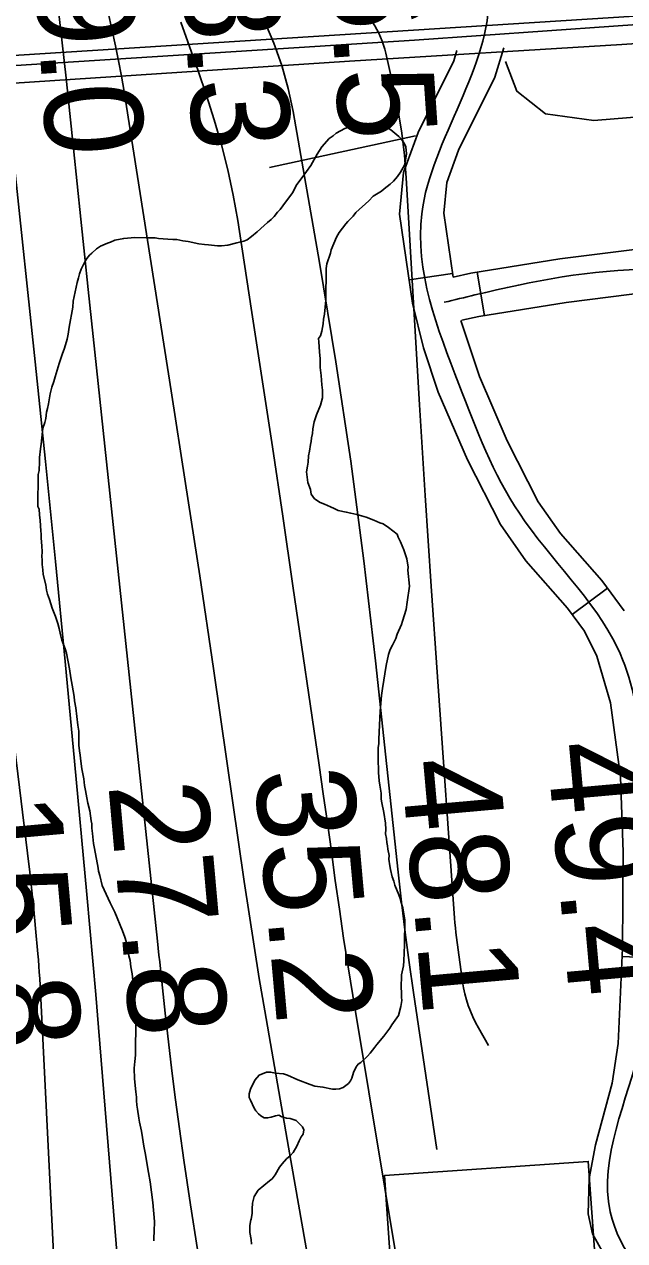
# Model space of a CAD drawing. Extents: x 3313442 to 3351311, y 721974 to 747360.
# Drawn here: x 3324727 to 3325136, y 729113 to 729942 of the extents above; entities that cross this region are included whole.
import ezdxf

# ---------------------------------------------------------------- set-up
doc = ezdxf.new("R2010")
doc.units = 0
for name, color, linetype in [('V-BLDG-OTLN', 7, 'Continuous'), ('V-BRDG-OTLN', 7, 'Continuous'), ('V-RIVR-RANG', 7, 'Continuous'), ('V-ROAD-CNTR', 7, 'Continuous'), ('V-SITE-VEGE', 7, 'Continuous'), ('V-TOPO-MAJR', 7, 'Continuous'), ('V-TOPO-MINR', 7, 'Continuous'), ('V-TOPO-SHOR', 7, 'Continuous')]:
    doc.layers.add(name, color=color, linetype=linetype)

msp = doc.modelspace()

# ---------------------------------------------------------------- linework, layer by layer
at = {"layer": 'V-BLDG-OTLN'}
msp.add_lwpolyline([(3324979.84, 729052.72), (3324972.54, 729157.11), (3325111.5, 729166.83), (3325118.81, 729062.45)], close=True, dxfattribs=at)
at = {"layer": 'V-BRDG-OTLN'}
for points in [[(3325676.61, 729961.93), (3325403.23, 729945.42), (3325134.28, 729927.72), (3324948.68, 729916.36), (3324716.77, 729901.2), (3324586.68, 729892.87), (3324582.42, 729979.53), (3324713.54, 729987.61), (3324937.54, 730002.27), (3325170.02, 730017.23), (3325371.06, 730029.8), (3325611.64, 730045.26), (3325891.58, 730062.67)], [(3320029.11, 729613.8), (3320339.22, 729634.27), (3320661.41, 729653.97), (3320967.6, 729674.61), (3321254.1, 729691.76), (3321493.35, 729708.2), (3321721.78, 729722.63), (3322170.54, 729751.36), (3322654.03, 729782.08), (3323222.6, 729817.79), (3323823.97, 729856.26), (3324302.83, 729887.22), (3324624.44, 729907.32), (3324993.14, 729930.83), (3325309.56, 729952.91), (3325623.66, 729972.5), (3325900.26, 729988.64)]]:
    msp.add_lwpolyline(points, dxfattribs=at)
at = {"layer": 'V-ROAD-CNTR'}
for p, q in [((3325040.64, 729743), (3325035.83, 729772.61)), ((3325019.02, 729771.78), (3324989.33, 729767.5)), ((3325124.51, 729557.34), (3325100.39, 729539.5)), ((3325164.42, 729305.07), (3325134.44, 729306.35))]:
    msp.add_line(p, q, dxfattribs=at)
for points in [[(3327244.32, 730080.97), (3325899.84, 729995.27), (3321914.87, 729742.58)], [(3325021.99, 729923.68), (3325019.83, 729916.59), (3324995.54, 729867.78), (3324985.54, 729840.53), (3324982.88, 729812.14), (3324991.63, 729751.57), (3324999.16, 729721.02), (3325009.26, 729690.9), (3325029.05, 729644.89), (3325051.62, 729600.66), (3325068.84, 729575.95), (3325097.3, 729543.68), (3325108.85, 729528.06), (3325117.35, 729511.11), (3325126.64, 729479.13), (3325133.54, 729428.9), (3325135.35, 729377.58), (3325134.69, 729312.1), (3325131.91, 729247.11), (3325127.73, 729220.19), (3325116.42, 729178.06), (3325112.07, 729155.23), (3325111.41, 729131.17), (3325114.31, 729117.4), (3325124.93, 729098.43)], [(3325053.92, 729925.55), (3325047.81, 729905.47), (3325023.14, 729855.89), (3325015.05, 729833.85), (3325013.08, 729812.89), (3325019.38, 729769.25)], [(3325658.28, 729822.55), (3325559.88, 729844.76), (3325493.97, 729854.26), (3325460.14, 729856.59), (3325426, 729855.59), (3325401.37, 729851.19), (3325367.02, 729839.46), (3325333.75, 729825.55), (3325315.67, 729816.24), (3325291.28, 729801.02), (3325280.26, 729795.35), (3325269.37, 729791.76), (3325242.55, 729788.69), (3325153.82, 729789.47), (3325092.19, 729781.78), (3325031.34, 729771.88), (3325019.38, 729769.25)], [(3325329.81, 729789.7), (3325306.1, 729774.9), (3325291.88, 729767.6), (3325275.85, 729762.3), (3325244.13, 729758.67), (3325155.55, 729759.45), (3325096.46, 729752.08), (3325036.98, 729742.4), (3325025.41, 729739.86)], [(3325024.54, 729739.67), (3325037.31, 729701.61), (3325056.22, 729657.65), (3325077.41, 729616.13), (3325092.48, 729594.51), (3325120.66, 729562.55), (3325135.88, 729541.97)]]:
    msp.add_lwpolyline(points, dxfattribs=at)
for points in [[(3326478.04, 730210.35), (3326482.35, 730403.29), (3326476.58, 730549.39), (3326473.61, 730637.71), (3326464.08, 730712.16), (3326370.96, 730713.71), (3326297.71, 730698.23), (3326169.71, 730725.9), (3326116.45, 730727.88), (3325982.64, 730689.67), (3325835.77, 730656.61), (3325666.24, 730661.4), (3325490.23, 730637.83), (3325403.5, 730634.84), (3325340.74, 730586.21), (3325201.43, 730523.99), (3325133.39, 730524.77), (3325012.9, 730513.46), (3324963.14, 730471.34), (3324981.93, 730365.88), (3324989.76, 730188.11), (3325009.72, 730055.84), (3325043.42, 729962.4), (3324997.98, 729812.51), (3325023.28, 729696.25), (3325064.51, 729608.4), (3325131.37, 729516.61), (3325150.36, 729377.77), (3325146.87, 729245.63), (3325126.45, 729132.53), (3325181.34, 729069.88), (3325338.87, 729062.31), (3325343.56, 728961.08), (3325372.85, 728878.06), (3325434.63, 728797.89), (3325537.34, 728748.77), (3325622.45, 728705.03), (3325714.6, 728675.45), (3325802.67, 728663.42), (3325976.26, 728695.07), (3326194.29, 728726.31), (3326466.63, 728765.32), (3326625.11, 728781.99), (3326781.78, 728849.74), (3326900.23, 728862.4), (3326981.75, 728872.83), (3327122.94, 728906.43), (3327349.99, 728934.63), (3327499.05, 728974.33), (3327515.65, 728986.69), (3327498, 729057.12), (3327490.77, 729119.3), (3327510.96, 729180.47), (3327588.76, 729283.84), (3327686.92, 729357.21), (3327753.03, 729377.43), (3327803.43, 729380.44), (3327847.87, 729388.87), (3327934.83, 729389.79), (3328039.14, 729390.23), (3328120.59, 729395.25), (3328249.21, 729403.96), (3328319.73, 729407.13), (3328384.24, 729401.49), (3328424.57, 729387.35), (3328470.08, 729368.59), (3328549.26, 729327.46), (3328661.09, 729275.68), (3328877.57, 729175.26), (3328980.19, 729125.77), (3329049.22, 729101.24), (3329067.8, 729104.63), (3329088.99, 729118.36), (3329113.61, 729147.02), (3329153.45, 729227.36), (3329182.49, 729301.19), (3329201.64, 729378.5), (3329199.66, 729471.18), (3329192.73, 729551.54), (3329166.92, 729646.66), (3329121.79, 729727.55), (3329091.49, 729778.71), (3329016.19, 729835.66), (3328941.73, 729880.13), (3328875.38, 729924.2), (3328789.67, 729967.9), (3328700.81, 730000.01), (3328643.56, 730009.51), (3328577.01, 730014.29), (3328435.19, 729993.91), (3328288.99, 729968.49), (3328169.46, 729944.48), (3328087.81, 729917.23), (3328042.9, 729880.41), (3327999.54, 729814.48), (3327967.22, 729727.08), (3328009.37, 729621.12)], [(3327455.61, 729777.77), (3327299.2, 729747.93), (3327231.33, 729750.07), (3327172.26, 729812.85), (3327115.65, 729890.62), (3326929.18, 729884.74), (3326778.26, 729875.26), (3326677.82, 729882.4), (3326518.7, 729881.16), (3326341.77, 729822.32), (3326240.47, 729767.06), (3326176.75, 729745.99), (3326056.79, 729783.32), (3325905.3, 729813.94), (3325785.04, 729804.98), (3325688.89, 729803.53), (3325557.16, 729830), (3325427.55, 729840.63), (3325340.08, 729811.94), (3325272.61, 729777.03), (3325154.68, 729774.46), (3325034.16, 729757.14), (3325013.34, 729752.14)], [(3325351.41, 729592.27), (3325302.24, 729587.13), (3325244.43, 729589.35), (3325190.04, 729576.79), (3325151.9, 729539.75), (3325158.25, 729396.51), (3325150.36, 729377.77)]]:
    msp.add_spline(points, degree=3, dxfattribs=at)
at = {"layer": 'V-SITE-VEGE'}
for points in [[(3324895.29, 729808.5), (3324897.42, 729810.59), (3324899.56, 729813.47), (3324901.43, 729815.3), (3324903.3, 729817.93), (3324909.98, 729826.84), (3324912.94, 729832.35), (3324916.42, 729837.07), (3324922.3, 729845.46), (3324926.6, 729853.08), (3324929.81, 729858.06), (3324934.88, 729863.82), (3324937.54, 729865.64), (3324939.67, 729867.47), (3324945.5, 729870.58), (3324952.92, 729872.89), (3324955.03, 729873.13), (3324963.75, 729873.84), (3324968.49, 729873.53), (3324972.71, 729872.17), (3324976.9, 729869.76), (3324982.4, 729865.22), (3324983.98, 729863.62), (3324986.32, 729860.17), (3324987.09, 729858.05), (3324987.57, 729853.29), (3324987, 729849.07), (3324986.18, 729845.65), (3324983.49, 729840.92), (3324981.35, 729837.78), (3324978.69, 729834.63)], [(3324978.69, 729834.63), (3324976.55, 729832.54), (3324972.3, 729829.41), (3324970.44, 729827.85), (3324964.86, 729824.47), (3324961.93, 729821.33), (3324953.14, 729813.23), (3324951.27, 729810.88), (3324947.54, 729807.21), (3324946.21, 729805.64), (3324941.67, 729799.61), (3324939.79, 729796.46), (3324936.27, 729787.79), (3324935.73, 729785.68), (3324933.28, 729778.31), (3324932.72, 729775.15), (3324932.52, 729753.51), (3324931.64, 729744.01), (3324931.08, 729740.59), (3324930.78, 729737.42), (3324929.95, 729732.42), (3324928.86, 729729.26), (3324927.52, 729727.43), (3324927.77, 729725.31), (3324928.23, 729718.44), (3324928.71, 729713.69), (3324928.65, 729707.62), (3324929.4, 729702.33), (3324929.87, 729695.99), (3324930.35, 729692.29), (3324930.31, 729687.02), (3324928.94, 729682.01), (3324926.24, 729675.44), (3324924.61, 729670.7), (3324923.77, 729665.96), (3324923.48, 729662.8), (3324922.92, 729659.9), (3324922.64, 729657.26), (3324922.09, 729655.15), (3324921.52, 729650.67), (3324920.7, 729647.51), (3324920.66, 729643.29), (3324920.1, 729640.39), (3324919.54, 729636.7), (3324920.26, 729629.3), (3324922.06, 729624.53), (3324922.56, 729621.37), (3324924.91, 729618.18), (3324928.84, 729615.76), (3324931.74, 729614.68), (3324935.68, 729612.79), (3324938.31, 729611.71), (3324940.93, 729610.37), (3324946.47, 729609.26), (3324949.63, 729608.44), (3324953.84, 729607.6), (3324960.16, 729605.7), (3324965.42, 729603.8), (3324969.36, 729601.92), (3324971.73, 729601.1), (3324975.4, 729598.69), (3324981.17, 729594.15), (3324981.94, 729592.03), (3324983.49, 729588.85), (3324985.82, 729583.55), (3324987.1, 729579.31), (3324987.87, 729577.46), (3324988.61, 729571.65), (3324988.59, 729569.53), (3324989.54, 729558.7), (3324988.12, 729547.89), (3324987.28, 729542.89), (3324984.83, 729534.99), (3324984.28, 729532.62), (3324981.31, 729526.05), (3324980.23, 729523.16), (3324978.08, 729518.43), (3324976.46, 729515.54), (3324975.38, 729512.11), (3324973.72, 729504.74), (3324971.2, 729488.93), (3324970.62, 729484.18), (3324969.73, 729473.63), (3324968.76, 729454.37), (3324968.73, 729451.47), (3324968.18, 729448.57), (3324968.34, 729438.01), (3324968.58, 729435.64), (3324968.54, 729431.67), (3324969.02, 729426.13), (3324969.52, 729423.22), (3324970.26, 729417.67), (3324970.22, 729413.71), (3324970.73, 729411.07), (3324972.25, 729404.45), (3324973.23, 729397.32), (3324973.46, 729392.83), (3324973.17, 729389.93), (3324973.93, 729386.75), (3324974.17, 729384.11), (3324974.67, 729381.73)], [(3324766.38, 729434.38), (3324765.64, 729439.4), (3324765.15, 729443.63), (3324764.65, 729446.53), (3324764.16, 729450.5), (3324764.25, 729460), (3324763.5, 729463.97), (3324762.29, 729475.86), (3324761.28, 729480.61), (3324761.04, 729483.52), (3324759.79, 729491.19), (3324758.79, 729496.21), (3324757.79, 729502.29), (3324755.78, 729513.13), (3324755.01, 729516.05), (3324752.69, 729521.87), (3324751.67, 729525.58), (3324750.92, 729529.81), (3324749.9, 729533.25), (3324748.36, 729538.01), (3324746.04, 729543.84), (3324744.25, 729549.67), (3324742.96, 729553.38), (3324742.19, 729556.02), (3324741.7, 729559.72), (3324739.92, 729566.6), (3324739.68, 729569.77), (3324739.19, 729573.47), (3324739.22, 729576.64), (3324738.98, 729579.02), (3324739.27, 729582.18), (3324739.05, 729586.14), (3324738.57, 729591.43), (3324738.59, 729594.06), (3324738.35, 729596.44), (3324737.89, 729603.58), (3324737.4, 729607.27), (3324737.17, 729611.24), (3324736.4, 729613.09), (3324736.6, 729634.73), (3324737.16, 729637.63), (3324737.48, 729643.44), (3324737.5, 729646.34), (3324738.09, 729652.4), (3324738.65, 729655.57), (3324739.8, 729666.38), (3324741.16, 729670.32), (3324741.71, 729672.96), (3324742.28, 729677.18), (3324742.83, 729679.81), (3324743.65, 729682.97), (3324744.78, 729689.82), (3324745.88, 729694.3), (3324747.23, 729698.25), (3324748.05, 729701.41), (3324750.78, 729710.35), (3324752.95, 729716.67), (3324754.57, 729720.87), (3324756.21, 729726.93), (3324757.04, 729730.35), (3324757.61, 729735.1), (3324760.11, 729748.8), (3324760.42, 729753.02), (3324763.18, 729765.67), (3324764, 729768.83), (3324764.81, 729771.46), (3324765.9, 729774.62), (3324766.71, 729776.45), (3324768.32, 729779.61), (3324769.67, 729781.97), (3324771.54, 729784.33), (3324773.13, 729785.63), (3324776.33, 729788.51), (3324778.98, 729790.33), (3324783.75, 729792.39), (3324785.87, 729793.17), (3324788.79, 729794.46), (3324794.87, 729795.72), (3324802.53, 729796.18), (3324810.45, 729796.1), (3324816.25, 729796.05), (3324818.62, 729795.5), (3324824.96, 729795.17), (3324828.38, 729794.88), (3324831.02, 729794.85), (3324835.24, 729794.02), (3324838.67, 729793.46), (3324846.04, 729792.07), (3324850, 729791.51), (3324852.64, 729791.22), (3324858.7, 729790.63), (3324861.6, 729790.6), (3324865.83, 729791.09), (3324871.92, 729792.62), (3324876.68, 729793.89), (3324879.06, 729794.66), (3324881.98, 729797.01), (3324885.71, 729800.14), (3324890.5, 729804.58), (3324892.9, 729806.41), (3324895.29, 729808.5)], [(3324815.35, 729112.68), (3324815.36, 729114.8), (3324815.67, 729119.02), (3324815.73, 729125.88), (3324814.8, 729138.82), (3324812.82, 729152.83), (3324811.82, 729159.17), (3324809.58, 729172.65), (3324808.56, 729177.15), (3324807.56, 729182.97), (3324807.08, 729187.46), (3324805.55, 729193.55), (3324805.04, 729196.19), (3324804.31, 729202.27), (3324803.81, 729205.18), (3324803.58, 729208.35), (3324803.6, 729210.46), (3324803.1, 729214.16), (3324802.13, 729223.14), (3324801.94, 729230.27), (3324802.51, 729234.75), (3324802.81, 729239.24), (3324803.04, 729263.52), (3324802.84, 729270.38), (3324802.14, 729279.36), (3324800.7, 729294.69), (3324799.69, 729299.45), (3324799.2, 729303.67), (3324798.44, 729306.85), (3324796.42, 729316.63), (3324795.65, 729319.55), (3324794.11, 729323.78), (3324788.69, 729336.5), (3324785.58, 729342.87), (3324780.15, 729354.8), (3324778.63, 729361.67), (3324777.6, 729364.59), (3324777.36, 729366.7), (3324774.84, 729379.92), (3324774.35, 729383.36), (3324773.62, 729390.23), (3324773.13, 729393.93), (3324773.16, 729396.83), (3324772.65, 729398.95), (3324771.66, 729405.56), (3324770.39, 729410.85), (3324769.63, 729414.55), (3324768.88, 729419.57), (3324768.12, 729423.01), (3324767.64, 729427.5), (3324766.38, 729434.38)], [(3324974.67, 729381.73), (3324974.92, 729379.62), (3324975.66, 729375.12), (3324975.64, 729372.75), (3324976.13, 729368.26), (3324976.63, 729365.61), (3324977.91, 729360.58), (3324978.94, 729357.67), (3324979.7, 729355.02), (3324982.27, 729348.4), (3324983.31, 729346.01), (3324983.82, 729343.9), (3324985.1, 729339.66), (3324986.34, 729331.2), (3324986.18, 729314.31), (3324985.81, 729303.5), (3324985.52, 729300.07), (3324984.14, 729294.01), (3324984.05, 729284.77), (3324984.29, 729282.4), (3324984.26, 729278.7), (3324984.5, 729276.32), (3324983.67, 729272.37), (3324982.03, 729266.31), (3324977.48, 729259.76), (3324976.14, 729257.66), (3324972.13, 729252.16), (3324967.32, 729246.39), (3324965.98, 729244.56), (3324962.78, 729240.63), (3324960.92, 729238.53), (3324956.38, 729234.09), (3324954.53, 729233.05), (3324953.19, 729231.22), (3324951.57, 729227.27), (3324950.22, 729223.59), (3324949.41, 729221.75), (3324948.07, 729219.92), (3324946.21, 729218.61), (3324944.35, 729217.05), (3324941.96, 729216.28), (3324939.32, 729216.04), (3324937.21, 729216.06), (3324930.62, 729217.44), (3324925.09, 729218.02), (3324921.93, 729219.11), (3324913.51, 729222.35), (3324906.42, 729225.59), (3324903.78, 729226.4), (3324897.98, 729226.99), (3324895.09, 729227.54), (3324892.18, 729227.57), (3324887.15, 729225.51), (3324884.21, 729222.1), (3324881.25, 729216.06), (3324880.43, 729212.9), (3324880.41, 729210.26), (3324881.18, 729208.41), (3324883.77, 729203.1), (3324884.81, 729201.24), (3324886.64, 729199.11), (3324888.21, 729197.78), (3324890.57, 729196.44), (3324892.95, 729196.42), (3324895.33, 729196.92), (3324898.24, 729197.95), (3324900.62, 729198.19), (3324902.72, 729197.12), (3324905.88, 729196.29), (3324908.25, 729196.01), (3324912.46, 729194.65), (3324916.64, 729190.39), (3324917.68, 729188.26), (3324917.12, 729185.36), (3324915.79, 729183.53), (3324914.44, 729180.91), (3324912.82, 729177.22), (3324910.41, 729172.76), (3324908.27, 729170.67), (3324905.88, 729168.58), (3324902.94, 729165.18), (3324901.07, 729162.82), (3324898.12, 729157.56), (3324895.98, 729154.95), (3324894.12, 729153.65), (3324886.41, 729147.12), (3324883.73, 729142.92), (3324882.63, 729138.44), (3324882.33, 729134.49), (3324882.3, 729131.58), (3324881.73, 729127.1), (3324881.47, 729127.11), (3324880.9, 729122.89), (3324880.86, 729118.4), (3324881.61, 729113.64), (3324881.84, 729110.47)]]:
    msp.add_lwpolyline(points, dxfattribs=at)
at = {"layer": 'V-TOPO-MAJR'}
msp.add_lwpolyline([(3324845.03, 729106.86), (3324840.34, 729137.21), (3324835.88, 729167.59), (3324832.86, 729189.07), (3324830.19, 729208.75), (3324827.65, 729228.45), (3324825.31, 729248.17), (3324823.1, 729267.9), (3324819.89, 729298.01), (3324819.39, 729302.7), (3324818.89, 729307.4), (3324818.39, 729312.09), (3324817.89, 729316.78), (3324770.66, 729760.84), (3324768.13, 729784.84), (3324765.62, 729808.84), (3324763.15, 729832.84), (3324760.7, 729856.85), (3324758.21, 729880.86), (3324755.63, 729904.85), (3324752.91, 729928.83), (3324750.11, 729952.8)], dxfattribs=at)
at = {"layer": 'V-TOPO-MINR'}
for points in [[(3324800.84, 728974.44), (3324777.7, 729257.93), (3324775.81, 729280.6), (3324773.87, 729303.26), (3324771.85, 729325.91), (3324769.79, 729348.56), (3324761.34, 729439.43), (3324754.9, 729507.5), (3324748.3, 729575.55), (3324741.46, 729643.58), (3324734.46, 729711.6), (3324720.29, 729847.02), (3324717.39, 729876.02), (3324714.69, 729905.03), (3324712.26, 729934.06), (3324710.02, 729963.11), (3324687.63, 730272.74), (3324687.41, 730275.62), (3324687.19, 730278.51), (3324686.96, 730281.39), (3324686.73, 730284.27), (3324686.38, 730288.4), (3324686.11, 730291.65), (3324658.43, 730619.77)], [(3324925.38, 729072.99), (3324916.14, 729124.68), (3324907.07, 729176.4), (3324890.99, 729269.3), (3324887.27, 729291.33), (3324883.68, 729313.38), (3324880.28, 729335.46), (3324877, 729357.56), (3324865.2, 729439.54), (3324856, 729502.63), (3324846.63, 729565.69), (3324837.02, 729628.72), (3324827.25, 729691.73), (3324796.83, 729885.47), (3324795.1, 729895.88), (3324793.27, 729906.26), (3324791.26, 729916.62), (3324789.15, 729926.96), (3324784.32, 729949.57)], [(3325005.6, 728951.7), (3324950.92, 729279.81), (3324947.75, 729299.39), (3324944.7, 729318.99), (3324941.82, 729338.61), (3324939.07, 729358.25), (3324936.38, 729377.9), (3324933.64, 729397.55), (3324930.85, 729417.19), (3324928.02, 729436.82), (3324910.2, 729559.05), (3324903.24, 729606.36), (3324896.2, 729653.66), (3324889.05, 729700.94), (3324881.81, 729748.21), (3324872.6, 729807.87), (3324869.51, 729825.21), (3324865.91, 729842.43), (3324861.52, 729859.46), (3324856.61, 729876.38), (3324851.18, 729893.15), (3324845.58, 729909.87), (3324839.72, 729926.5), (3324833.69, 729943.07)], [(3325008.32, 729175.01), (3324992.35, 729281.86), (3324989.42, 729302.34), (3324986.66, 729322.84), (3324984.16, 729343.38), (3324981.83, 729363.94), (3324966.42, 729507.91), (3324958.46, 729575.94), (3324949.59, 729643.85), (3324939.39, 729711.57), (3324928.29, 729779.16), (3324910.33, 729882.08), (3324906.9, 729897.92), (3324902.64, 729913.5), (3324897.13, 729928.68), (3324890.8, 729943.6)], [(3325043.49, 729245.81), (3325036.55, 729257.85), (3325034.57, 729261.51), (3325032.73, 729265.24), (3325031.12, 729269.07), (3325029.64, 729272.97), (3325028.4, 729276.94), (3325027.32, 729280.95), (3325026.48, 729285.02), (3325025.8, 729289.13), (3325021.72, 729319.4), (3325021.31, 729322.69), (3325020.94, 729325.98), (3325020.63, 729329.28), (3325020.37, 729332.59), (3325008.7, 729496.96), (3325004.44, 729558.71), (3325000.34, 729620.48), (3324996.48, 729682.27), (3324992.78, 729744.06), (3324987.39, 729837.06), (3324986.14, 729852.31), (3324984.39, 729867.49), (3324981.91, 729882.57), (3324978.93, 729897.58), (3324973.51, 729921.8), (3324972.8, 729924.63), (3324971.98, 729927.42), (3324971.01, 729930.16), (3324969.94, 729932.86), (3324968.71, 729935.5), (3324967.38, 729938.09), (3324965.9, 729940.58), (3324964.31, 729943.03)], [(3324748.24, 729081.6), (3324744.56, 729154.36), (3324737.57, 729291.41), (3324737.33, 729295.64), (3324737.06, 729299.87), (3324736.73, 729304.1), (3324736.37, 729308.32), (3324734.8, 729325.53), (3324733.57, 729338.35), (3324732.27, 729351.16), (3324730.84, 729363.95), (3324729.33, 729376.74), (3324712.63, 729512.75)]]:
    msp.add_lwpolyline(points, dxfattribs=at)
at = {"layer": 'V-TOPO-SHOR'}
msp.add_line((3324993.79, 729865.65), (3324894.31, 729844.02), dxfattribs=at)
msp.add_lwpolyline([(3325055.16, 729916.32), (3325062.78, 729895.96), (3325082.39, 729880.54), (3325115.37, 729875.93), (3325217.96, 729884.45), (3325347.97, 729917.52), (3325587.95, 729931.08)], dxfattribs=at)

# ---------------------------------------------------------------- texts
at = {"layer": 'V-RIVR-RANG'}
for s, rotation, p in [('46.5', 273.89833, (3324930.51, 730035.06)), ('29.0', 273.89833, (3324730.81, 730023.88)), ('38.3', 273.89833, (3324830.76, 730028.02)), ('49.4', 275.11833, (3325083.06, 729450.98)), ('35.2', 275.11833, (3324883.9, 729432.66)), ('48.1', 275.11833, (3324983.7, 729439.45)), ('27.8', 275.11833, (3324784.33, 729423.49)), ('15.8', 275.11833, (3324684.75, 729414.33))]:
    msp.add_text(s, height=67, rotation=rotation, dxfattribs=at).set_placement(p)

doc.saveas('drawing.dxf')
